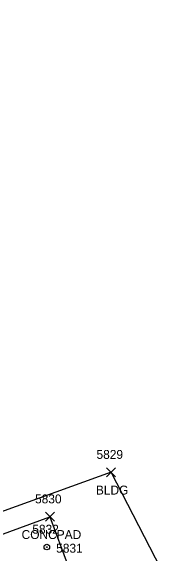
# Model space of a CAD drawing. Extents: x 1769141 to 1770911, y 735471 to 741449.
# Drawn here: x 1770491.1 to 1770529.7, y 740275.1 to 740396.8 of the extents above; entities that cross this region are included whole.
import ezdxf

# ---------------------------------------------------------------- set-up
doc = ezdxf.new("R2010")
doc.units = 0
for name, color, linetype in [('L_A', 7, 'Continuous'), ('L_I', 7, 'Continuous'), ('L_TIC', 7, 'Continuous'), ('LBC', 7, 'Continuous'), ('LS', 7, 'Continuous'), ('LSOGP', 7, 'Continuous'), ('R_I', 7, 'Continuous'), ('U_I', 7, 'Continuous'), ('UWW', 7, 'Continuous')]:
    doc.layers.add(name, color=color, linetype=linetype)

msp = doc.modelspace()

# ---------------------------------------------------------------- linework, layer by layer
at = {"layer": 'L_TIC'}
for points in [[(1770512.53, 740292.28), (1770514.53, 740294.28)], [(1770514.53, 740292.28), (1770512.53, 740294.28)], [(1770498.82, 740282.3), (1770500.82, 740284.3)], [(1770500.82, 740282.3), (1770498.82, 740284.3)]]:
    msp.add_lwpolyline(points, dxfattribs=at)
at = {"layer": 'LBC'}
msp.add_lwpolyline([(1770513.53, 740293.28), (1770479.74, 740281.13), (1770479.55, 740281.34), (1770470.33, 740307.12), (1770463.79, 740305.3), (1770456.68, 740324.59), (1770456.22, 740325.23), (1770448.9, 740347.59), (1770448.76, 740347.79), (1770443.89, 740362.42), (1770471.04, 740372.15)], dxfattribs=at)
at = {"layer": 'LS'}
for points in [[(1770499.82, 740283.3), (1770503.91, 740272.24), (1770462.96, 740257.06), (1770458.75, 740268.28)], [(1770458.75, 740268.28), (1770499.82, 740283.3)]]:
    msp.add_lwpolyline(points, dxfattribs=at)
at = {"layer": 'LSOGP'}
msp.add_lwpolyline([(1770529.68, 740262), (1770513.53, 740293.28), (1770479.74, 740281.13), (1770479.55, 740281.34), (1770470.33, 740307.12), (1770463.79, 740305.3), (1770456.68, 740324.59), (1770456.22, 740325.23), (1770448.9, 740347.59), (1770448.76, 740347.79), (1770443.89, 740362.42), (1770471.04, 740372.15), (1770461.26, 740381.76), (1770439.6, 740402.54)], dxfattribs=at)
at = {"layer": 'UWW'}
for radius in [0.625, 0.0833]:
    msp.add_circle((1770499.13, 740276.5), radius, dxfattribs=at)

# ---------------------------------------------------------------- texts
at = {"layer": 'L_A'}
for s, p in [('BLDG', (1770510.12, 740288.28)), ('CONCPAD', (1770493.47, 740278.3))]:
    msp.add_text(s, height=2, dxfattribs=at).set_placement(p)
at = {"layer": 'L_I'}
for s, p in [('5829', (1770510.26, 740296.28)), ('5830', (1770496.48, 740286.3)), ('5831', (1770501.22, 740275.24))]:
    msp.add_text(s, height=2, dxfattribs=at).set_placement(p)
at = {"layer": 'R_I'}
msp.add_text('5831', height=2, dxfattribs=at).set_placement((1770501.22, 740275.24))
at = {"layer": 'U_I'}
msp.add_text('5832', height=2, dxfattribs=at).set_placement((1770495.87, 740279.5))

doc.saveas('drawing.dxf')
